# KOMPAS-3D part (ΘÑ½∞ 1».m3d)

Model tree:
1. Эскиз:1
2. Операция выдавливания:1
     Расстояние 1 = 2
3. Эскиз:2
4. Операция выдавливания:2
     Расстояние 1 = 5
5. Эскиз:3
6. Операция выдавливания:3
     Расстояние 1 = 2
7. Эскиз:4
8. Операция выдавливания:4
     Расстояние 1 = 78
9. Эскиз:5
10. Операция выдавливания:5
     Расстояние 1 = 2
11. Эскиз:6
12. Операция выдавливания:6
     Расстояние 1 = 4.5
13. Эскиз:7
14. Операция выдавливания:7
     Расстояние 1 = 2
15. Скругление:1
     Радиус = 1
16. Скругление:2
     Радиус = 1
17. Эскиз:8
18. Вырезать элемент выдавливания:1
     Расстояние 1 = 10; Угол 1 = 35
19. Эскиз:9
20. Вырезать элемент выдавливания:2
     Расстояние 1 = 10; Угол 1 = 35
21. Эскиз:10
22. Вырезать элемент выдавливания:3
     Расстояние 2 = 22; Расстояние 1 = 22; Угол 1 = 35
23. Эскиз:11
24. Вырезать элемент выдавливания:4
     Расстояние 2 = 2; Расстояние 1 = 2
25. Эскиз:12
26. Вырезать элемент выдавливания:5
     Расстояние 2 = 2; Расстояние 1 = 2; Угол 1 = 35
27. Эскиз:13
28. Вырезать элемент выдавливания:6
     Расстояние 2 = 2; Расстояние 1 = 122
29. Эскиз:14
30. Вырезать элемент выдавливания:7
     Расстояние 2 = 140; Расстояние 1 = 10
31. Эскиз:15
32. Вырезать элемент выдавливания:8
     Расстояние 1 = 10
33. Скругление:3
     Радиус = 2
